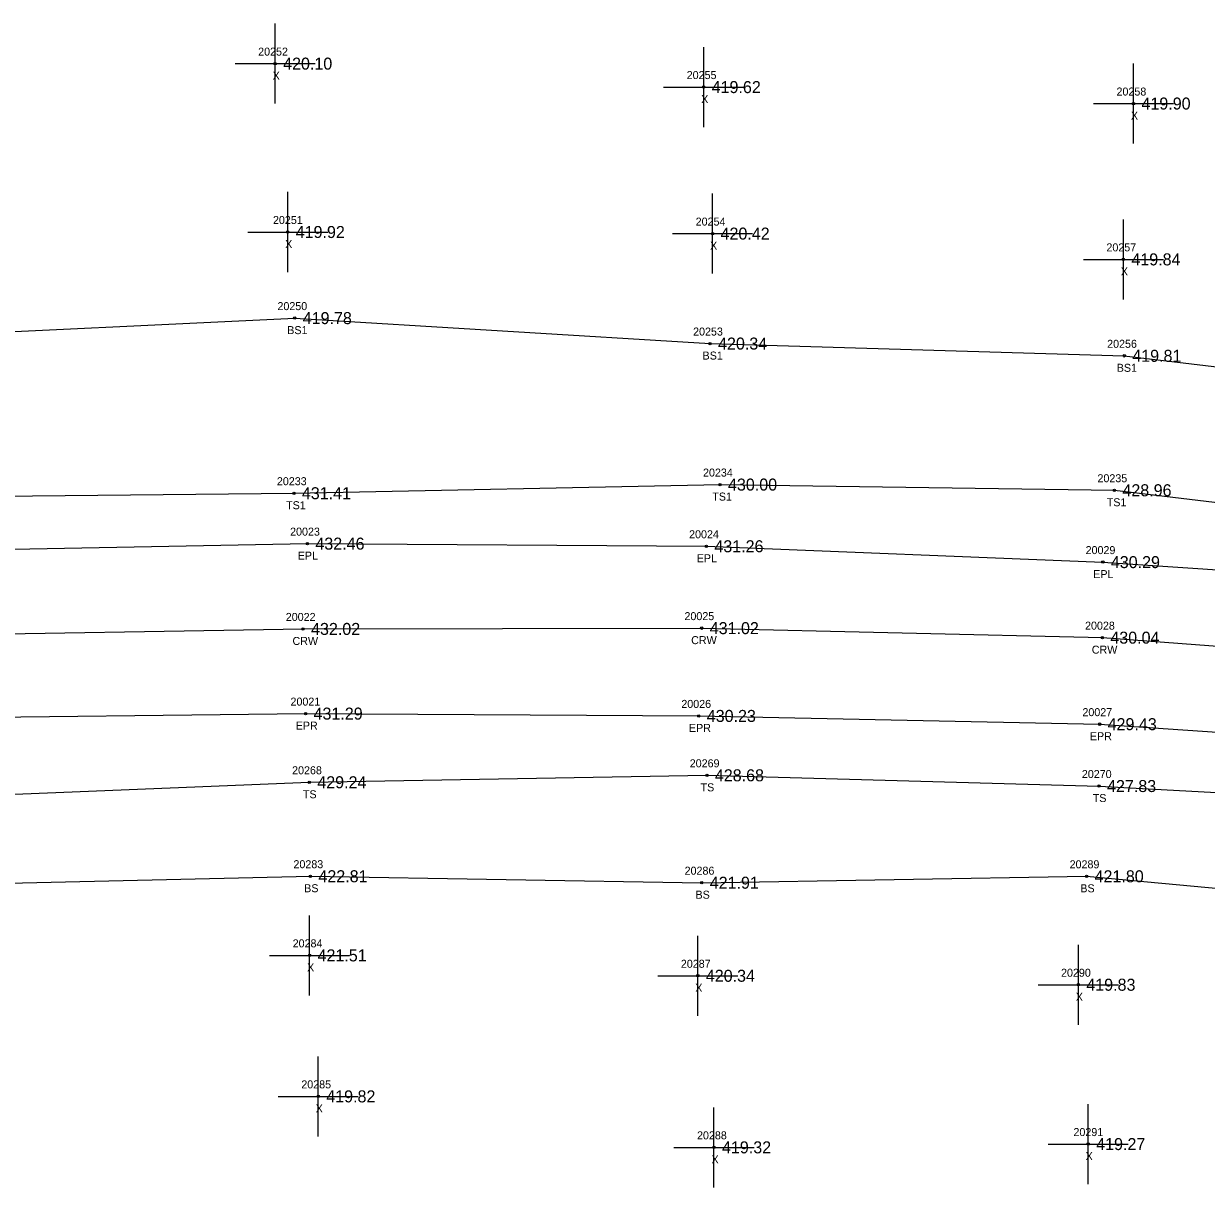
# Model space of a CAD drawing. Extents: x 1613184 to 1614731, y 770859 to 771868.
# Drawn here: x 1613657.4 to 1613805.1, y 771286.9 to 771432.3 of the extents above; entities that cross this region are included whole.
import ezdxf

# ---------------------------------------------------------------- set-up
doc = ezdxf.new("R2010")
doc.units = 0
for name, color, linetype in [('RD_DTM_BkLn1', 7, 'Continuous'), ('RD_DTM_BkLn2', 7, 'Continuous'), ('RD_DTM_BkLn_txCode', 7, 'Continuous'), ('RD_EX_Misc', 7, 'Continuous'), ('RD_EX_Misc_txCode', 7, 'Continuous'), ('RD_EX_Road', 7, 'Continuous'), ('RD_EX_Road_txCode', 7, 'Continuous'), ('RD_EX_TX_Misc_ELEV', 7, 'Continuous'), ('RD_EX_TX_Road_ELEV', 7, 'Continuous'), ('RD_HC_Survey_ELEV', 7, 'Continuous'), ('RD_HC_Survey_txCode', 7, 'Continuous'), ('RD_SMD_Locator', 7, 'Continuous')]:
    doc.layers.add(name, color=color, linetype=linetype)

msp = doc.modelspace()

# ---------------------------------------------------------------- linework, layer by layer
at = {"layer": 'RD_DTM_BkLn1'}
msp.add_lwpolyline([(1613193.64, 771319.41), (1613293.11, 771329.14), (1613392.46, 771338.5), (1613492.95, 771347.08), (1613542.61, 771350.97), (1613592.52, 771354.09), (1613642.63, 771355.86), (1613692.27, 771356.69), (1613742.08, 771356.79), (1613792.13, 771355.6), (1613841.94, 771351.86), (1613890.87, 771346.48)], dxfattribs=at)
at = {"layer": 'RD_DTM_BkLn2'}
for points in [[(1613191.9, 771337.48), (1613291.44, 771345.53), (1613389.08, 771355.5), (1613435.73, 771361.94), (1613448.05, 771379.9), (1613456.58, 771373.81), (1613489.82, 771379.95), (1613539.65, 771385.9), (1613590.16, 771390.66), (1613642.18, 771393.2), (1613691.23, 771395.53), (1613743.12, 771392.35), (1613794.87, 771390.82), (1613846.37, 771384.69), (1613895.3, 771384.28), (1613914.84, 771377.38)], [(1613192.28, 771333.37), (1613291.74, 771342.64), (1613389.11, 771353.66), (1613436.85, 771356.33), (1613492.16, 771363.71), (1613540.47, 771367.11), (1613591.24, 771372.7), (1613642.11, 771373.16), (1613691.12, 771373.65), (1613744.36, 771374.73), (1613793.64, 771374.02), (1613845.39, 771367.84), (1613892.43, 771366.82), (1613891.67, 771360.8)], [(1613513, 771333.25), (1613544.25, 771334.4), (1613593.37, 771335.17), (1613642.92, 771335.51), (1613693.05, 771337.53), (1613742.72, 771338.4), (1613791.72, 771337.06), (1613840.42, 771334.43), (1613870.28, 771332.34), (1613884.67, 771331.69), (1613888.61, 771333.71)], [(1613531.71, 771317.92), (1613595.86, 771321.39), (1613644.57, 771324.66), (1613693.19, 771325.79), (1613742.08, 771324.98), (1613790.16, 771325.78), (1613839.02, 771321.26), (1613886.56, 771314.77), (1613914.71, 771327.05)]]:
    msp.add_lwpolyline(points, dxfattribs=at)
at = {"layer": 'RD_EX_Misc'}
for p, q in [((1613688.78, 771422.33), (1613688.78, 771432.33)), ((1613742.32, 771419.4), (1613742.32, 771429.4)), ((1613683.78, 771427.33), (1613693.78, 771427.33)), ((1613796.02, 771417.34), (1613796.02, 771427.34)), ((1613737.32, 771424.4), (1613747.32, 771424.4)), ((1613791.02, 771422.34), (1613801.02, 771422.34)), ((1613690.35, 771401.29), (1613690.35, 771411.29)), ((1613743.43, 771401.09), (1613743.43, 771411.09)), ((1613794.76, 771397.87), (1613794.76, 771407.87)), ((1613685.35, 771406.29), (1613695.35, 771406.29)), ((1613738.43, 771406.09), (1613748.43, 771406.09)), ((1613789.76, 771402.87), (1613799.76, 771402.87)), ((1613693.08, 771310.9), (1613693.08, 771320.9)), ((1613741.59, 771308.35), (1613741.59, 771318.35)), ((1613789.13, 771307.23), (1613789.13, 771317.23)), ((1613688.08, 771315.9), (1613698.08, 771315.9)), ((1613736.59, 771313.35), (1613746.59, 771313.35)), ((1613784.13, 771312.23), (1613794.13, 771312.23)), ((1613694.17, 771293.28), (1613694.17, 771303.28)), ((1613689.17, 771298.28), (1613699.17, 771298.28)), ((1613743.61, 771286.91), (1613743.61, 771296.91)), ((1613790.36, 771287.32), (1613790.36, 771297.32)), ((1613785.36, 771292.32), (1613795.36, 771292.32)), ((1613738.61, 771291.91), (1613748.61, 771291.91))]:
    msp.add_line(p, q, dxfattribs=at)
at = {"layer": 'RD_EX_Road'}
for points in [[(1613192.48, 771329.15), (1613292.05, 771338.23), (1613391, 771348.45), (1613492.61, 771357.17), (1613541.86, 771361.21), (1613591.56, 771364.71), (1613642.92, 771366.4), (1613692.81, 771367.35), (1613742.66, 771367.02), (1613792.19, 771365.04), (1613843.32, 771361.63), (1613887.78, 771357.57), (1613892.3, 771358.63)], [(1613194.6, 771309.27), (1613294.55, 771318.15), (1613393.75, 771328.31), (1613493.74, 771336.74), (1613544.27, 771340.57), (1613593.48, 771343.76), (1613642.77, 771345.54), (1613692.58, 771346.11), (1613741.71, 771345.82), (1613791.79, 771344.79), (1613840.79, 771341.46), (1613889.25, 771335.84)]]:
    msp.add_lwpolyline(points, dxfattribs=at)
at = {"layer": 'RD_SMD_Locator'}
for centre in [(1613688.78, 771427.33), (1613742.32, 771424.4), (1613796.02, 771422.34), (1613690.35, 771406.29), (1613743.43, 771406.09), (1613794.76, 771402.87), (1613691.23, 771395.53), (1613743.12, 771392.35), (1613794.87, 771390.82), (1613744.36, 771374.73), (1613691.12, 771373.65), (1613793.64, 771374.02), (1613692.81, 771367.35), (1613742.66, 771367.02), (1613792.19, 771365.04), (1613692.27, 771356.69), (1613742.08, 771356.79), (1613792.13, 771355.6), (1613692.58, 771346.11), (1613741.71, 771345.82), (1613791.79, 771344.79), (1613742.72, 771338.4), (1613693.05, 771337.53), (1613791.72, 771337.06), (1613693.19, 771325.79), (1613742.08, 771324.98), (1613790.16, 771325.78), (1613693.08, 771315.9), (1613741.59, 771313.35), (1613789.13, 771312.23), (1613694.17, 771298.28), (1613743.61, 771291.91), (1613790.36, 771292.32)]:
    msp.add_circle(centre, 0.15, dxfattribs=at)

# ---------------------------------------------------------------- texts
at = {"layer": 'RD_DTM_BkLn_txCode'}
for s, p in [('20250', (1613689.07, 771396.53)), ('BS1', (1613690.29, 771393.53)), ('20253', (1613741, 771393.35)), ('20256', (1613792.73, 771391.82)), ('BS1', (1613742.18, 771390.35)), ('BS1', (1613793.93, 771388.82)), ('20234', (1613742.24, 771375.73)), ('20233', (1613689, 771374.65)), ('20235', (1613791.52, 771375.02)), ('TS1', (1613743.4, 771372.73)), ('TS1', (1613690.15, 771371.65)), ('TS1', (1613792.68, 771372.02)), ('20268', (1613690.9, 771338.53)), ('20269', (1613740.58, 771339.4)), ('20270', (1613789.57, 771338.06)), ('TS', (1613692.25, 771335.53)), ('TS', (1613741.93, 771336.4)), ('TS', (1613790.93, 771335.06)), ('20283', (1613691.07, 771326.79)), ('20289', (1613788.04, 771326.78)), ('20286', (1613739.94, 771325.98)), ('BS', (1613692.41, 771323.79)), ('BS', (1613789.38, 771323.78)), ('BS', (1613741.3, 771322.98))]:
    msp.add_text(s, height=1, dxfattribs=at).set_placement(p)
at = {"layer": 'RD_EX_Misc_txCode'}
for s, p in [('20252', (1613686.66, 771428.33)), ('X', (1613688.47, 771425.33)), ('20255', (1613740.2, 771425.4)), ('20258', (1613793.9, 771423.34)), ('X', (1613742.01, 771422.4)), ('X', (1613795.7, 771420.34)), ('20251', (1613688.51, 771407.29)), ('20254', (1613741.32, 771407.09)), ('X', (1613690.03, 771404.29)), ('X', (1613743.12, 771404.09)), ('20257', (1613792.64, 771403.87)), ('X', (1613794.44, 771400.87)), ('20284', (1613690.97, 771316.9)), ('X', (1613692.77, 771313.9)), ('20287', (1613739.47, 771314.35)), ('20290', (1613786.97, 771313.23)), ('X', (1613741.27, 771311.35)), ('X', (1613788.81, 771310.23)), ('20285', (1613692.05, 771299.28)), ('X', (1613693.85, 771296.28)), ('20288', (1613741.49, 771292.91)), ('20291', (1613788.52, 771293.32)), ('X', (1613743.3, 771289.91)), ('X', (1613790.04, 771290.32))]:
    msp.add_text(s, height=1, dxfattribs=at).set_placement(p)
at = {"layer": 'RD_EX_Road_txCode'}
for s, p in [('20023', (1613690.65, 771368.35)), ('20024', (1613740.5, 771368.02)), ('EPL', (1613691.6, 771365.35)), ('EPL', (1613741.45, 771365.02)), ('20029', (1613790.04, 771366.04)), ('EPL', (1613790.99, 771363.04)), ('20021', (1613690.7, 771347.11)), ('20026', (1613739.53, 771346.82)), ('20027', (1613789.64, 771345.79)), ('EPR', (1613691.35, 771344.11)), ('EPR', (1613740.48, 771343.82)), ('EPR', (1613790.57, 771342.79))]:
    msp.add_text(s, height=1, dxfattribs=at).set_placement(p)
at = {"layer": 'RD_EX_TX_Misc_ELEV'}
for s, p in [('420.10', (1613689.78, 771426.58)), ('419.62', (1613743.32, 771423.65)), ('419.90', (1613797.02, 771421.59)), ('419.92', (1613691.35, 771405.54)), ('420.42', (1613744.43, 771405.34)), ('419.84', (1613795.76, 771402.12)), ('419.78', (1613692.23, 771394.78)), ('420.34', (1613744.12, 771391.6)), ('419.81', (1613795.87, 771390.07)), ('430.00', (1613745.36, 771373.98)), ('428.96', (1613794.64, 771373.27)), ('431.41', (1613692.12, 771372.9)), ('429.24', (1613694.05, 771336.78)), ('428.68', (1613743.72, 771337.65)), ('427.83', (1613792.72, 771336.31)), ('422.81', (1613694.19, 771325.04)), ('421.80', (1613791.16, 771325.03)), ('421.91', (1613743.08, 771324.23)), ('421.51', (1613694.08, 771315.15)), ('420.34', (1613742.59, 771312.6)), ('419.83', (1613790.13, 771311.48)), ('419.82', (1613695.17, 771297.53)), ('419.32', (1613744.61, 771291.16)), ('419.27', (1613791.36, 771291.57))]:
    msp.add_text(s, height=1.5, dxfattribs=at).set_placement(p)
at = {"layer": 'RD_EX_TX_Road_ELEV'}
for s, p in [('432.46', (1613693.81, 771366.6)), ('431.26', (1613743.66, 771366.27)), ('430.29', (1613793.19, 771364.29)), ('431.29', (1613693.58, 771345.36)), ('430.23', (1613742.71, 771345.07)), ('429.43', (1613792.79, 771344.04))]:
    msp.add_text(s, height=1.5, dxfattribs=at).set_placement(p)
at = {"layer": 'RD_HC_Survey_ELEV'}
for s, p in [('432.02', (1613693.27, 771355.94)), ('431.02', (1613743.08, 771356.04)), ('430.04', (1613793.13, 771354.85))]:
    msp.add_text(s, height=1.5, dxfattribs=at).set_placement(p)
at = {"layer": 'RD_HC_Survey_txCode'}
for s, p in [('20022', (1613690.11, 771357.69)), ('20025', (1613739.92, 771357.79)), ('20028', (1613789.97, 771356.6)), ('CRW', (1613690.95, 771354.69)), ('CRW', (1613740.76, 771354.79)), ('CRW', (1613790.81, 771353.6))]:
    msp.add_text(s, height=1, dxfattribs=at).set_placement(p)

doc.saveas('drawing.dxf')
